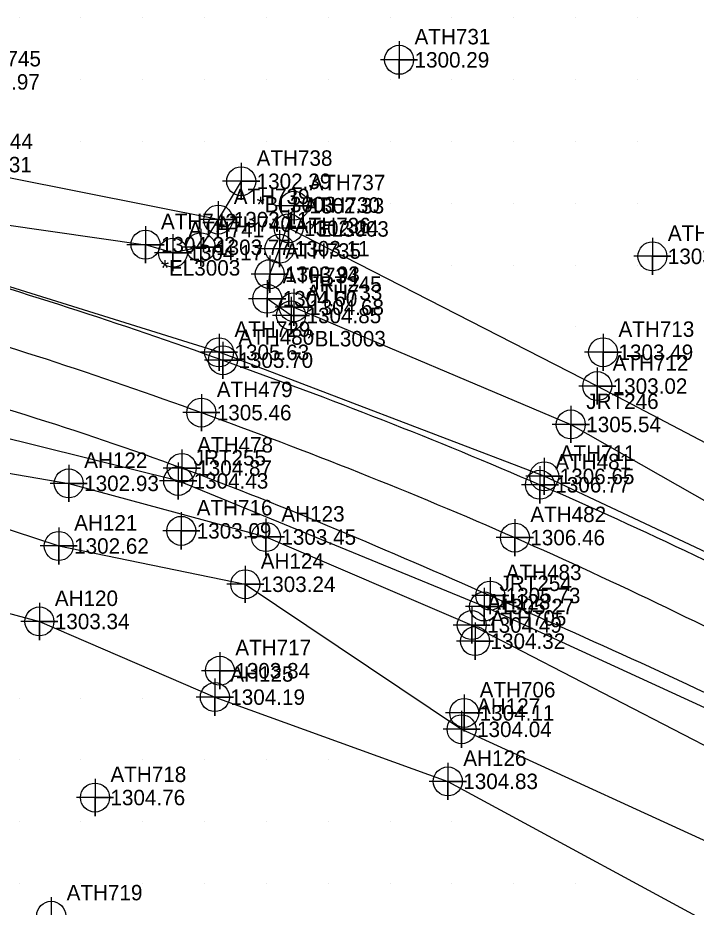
# Model space of a CAD drawing. Extents: x 1234484 to 1235382, y 695050 to 695510.
# Drawn here: x 1235049.8 to 1235159.5, y 695206.2 to 695350 of the extents above; entities that cross this region are included whole.
import ezdxf

# ---------------------------------------------------------------- set-up
doc = ezdxf.new("R2010")
doc.units = 0
for name, color, linetype in [('Exist DTM Breakline', 7, 'Continuous'), ('Exist DTM Breakline Cogo Elevation', 7, 'Continuous'), ('Exist DTM Breakline Cogo Number', 7, 'Continuous'), ('Exist DTM Breakline Cogo Point CELL', 7, 'Continuous'), ('Exist DTM Breakline Underwater', 7, 'Continuous'), ('Exist DTM Crownline', 7, 'Continuous'), ('Exist DTM Crownline Cogo Elevation', 7, 'Continuous'), ('Exist DTM Crownline Cogo Number', 7, 'Continuous'), ('Exist DTM Crownline Cogo Point CELL', 7, 'Continuous'), ('Exist DTM Drainline Cogo Elevation', 7, 'Continuous'), ('Exist DTM Drainline Cogo Number', 7, 'Continuous'), ('Exist DTM Drainline Cogo Point CELL', 7, 'Continuous'), ('Exist DTM QL2 LIDAR Elevation Point', 7, 'Continuous'), ('Exist DTM Regular Point CELL', 7, 'Continuous'), ('Exist DTM Regular Point Cogo Elevation', 7, 'Continuous'), ('Exist DTM Regular Point Cogo Number', 7, 'Continuous'), ('Exist DTM Regular Point Underwater CELL', 7, 'Continuous'), ('Exist DTM Regular Point Underwater Cogo Elevation', 7, 'Continuous'), ('Exist DTM Regular Point Underwater Cogo Number', 7, 'Continuous'), ('Exist Hydro Stream or Body of Water', 7, 'Continuous'), ('Exist Roads EOP', 7, 'Continuous'), ('Exist Roads EOP Cogo Elevation', 7, 'Continuous'), ('Exist Roads EOP Cogo Number', 7, 'Continuous'), ('Exist Roads EOP Cogo Point CELL', 7, 'Continuous'), ('Exist Roads EOP Other', 7, 'Continuous'), ('Exist Roads EOP Other Cogo Comment', 7, 'Continuous'), ('Exist Roads EOP Other Cogo Elevation', 7, 'Continuous'), ('Exist Roads EOP Other Cogo Number', 7, 'Continuous'), ('Exist Roads EOP Other Cogo Point CELL', 7, 'Continuous')]:
    doc.layers.add(name, color=color, linetype=linetype)

msp = doc.modelspace()

# ---------------------------------------------------------------- linework, layer by layer
at = {"layer": 'Exist DTM Breakline'}
for points in [[(1235082.217, 695317.363), (1235037.46, 695326.259), (1235017.524, 695333.883)], [(1235011.557, 695329.402), (1235031.782, 695318.825), (1235070.444, 695313.308)], [(1235319.256, 695177.55), (1235278.534, 695201.47), (1235237.781, 695224.217), (1235188.481, 695250.698), (1235134.96, 695275.849), (1235082.338, 695295.901), (1235034.938, 695310.723), (1234997.435, 695322.999)], [(1235324.566, 695184.553), (1235284.54, 695210.684), (1235243.923, 695233.555), (1235196.6, 695262.635), (1235143.527, 695290.446), (1235093.587, 695315.971)], [(1235094.433, 695303.192), (1235139.249, 695284.24), (1235185.145, 695258.152), (1235235.18, 695232.365), (1235270.796, 695206.904), (1235315.147, 695184.076)], [(1235258.778, 695187.05), (1235221.35, 695207.416), (1235173.519, 695232.644), (1235125.211, 695254.804), (1235075.73, 695275.107), (1235023.735, 695288.012), (1234968.789, 695301.22)]]:
    msp.add_lwpolyline(points, dxfattribs=at)
at = {"layer": 'Exist DTM Breakline Cogo Point CELL'}
for points in [[(1235093.587, 695318.971), (1235093.587, 695312.971), (1235093.587, 695315.971), (1235096.587, 695315.971), (1235090.587, 695315.971)], [(1235094.433, 695306.192), (1235094.433, 695300.192), (1235094.433, 695303.192), (1235097.433, 695303.192), (1235091.433, 695303.192)], [(1235082.338, 695298.901), (1235082.338, 695292.901), (1235082.338, 695295.901), (1235085.338, 695295.901), (1235079.338, 695295.901)], [(1235143.527, 695293.446), (1235143.527, 695287.446), (1235143.527, 695290.446), (1235146.527, 695290.446), (1235140.527, 695290.446)], [(1235139.249, 695287.24), (1235139.249, 695281.24), (1235139.249, 695284.24), (1235142.249, 695284.24), (1235136.249, 695284.24)], [(1235134.96, 695278.849), (1235134.96, 695272.849), (1235134.96, 695275.849), (1235137.96, 695275.849), (1235131.96, 695275.849)], [(1235075.73, 695278.107), (1235075.73, 695272.107), (1235075.73, 695275.107), (1235078.73, 695275.107), (1235072.73, 695275.107)], [(1235076.225, 695270.03), (1235076.225, 695264.03), (1235076.225, 695267.03), (1235079.225, 695267.03), (1235073.225, 695267.03)], [(1235125.211, 695257.804), (1235125.211, 695251.804), (1235125.211, 695254.804), (1235128.211, 695254.804), (1235122.211, 695254.804)], [(1235123.766, 695252.2), (1235123.766, 695246.2), (1235123.766, 695249.2), (1235126.766, 695249.2), (1235120.766, 695249.2)], [(1235055.183, 695207.784), (1235055.183, 695201.784), (1235055.183, 695204.784), (1235058.183, 695204.784), (1235052.183, 695204.784)]]:
    msp.add_lwpolyline(points, dxfattribs=at)
for centre in [(1235093.587, 695315.971), (1235094.433, 695303.192), (1235082.338, 695295.901), (1235143.527, 695290.446), (1235139.249, 695284.24), (1235075.73, 695275.107), (1235134.96, 695275.849), (1235076.225, 695267.03), (1235125.211, 695254.804), (1235123.766, 695249.2), (1235055.183, 695204.784)]:
    msp.add_circle(centre, 2.344, dxfattribs=at)
at = {"layer": 'Exist DTM Breakline Underwater'}
msp.add_lwpolyline([(1234948.239, 695292.841), (1234952.805, 695292.84), (1234960.83, 695292.864), (1234972.599, 695288.481), (1235023.203, 695275.502), (1235056.399, 695264.585), (1235086.587, 695258.395), (1235121.582, 695234.941), (1235168.445, 695213.485), (1235191.313, 695204.186), (1235209.05, 695188.429), (1235246.922, 695166.749), (1235265.478, 695149.496)], dxfattribs=at)
at = {"layer": 'Exist DTM Crownline'}
msp.add_spline([(1234978.534, 695313.159), (1235028.867, 695302.317), (1235079.475, 695286.154), (1235130.202, 695265.942), (1235178.94, 695242.599), (1235226.8, 695217.474)], degree=3, dxfattribs=at)
at = {"layer": 'Exist DTM Crownline Cogo Point CELL'}
for points in [[(1235079.475, 695289.154), (1235079.475, 695283.154), (1235079.475, 695286.154), (1235082.475, 695286.154), (1235076.475, 695286.154)], [(1235130.202, 695268.942), (1235130.202, 695262.942), (1235130.202, 695265.942), (1235133.202, 695265.942), (1235127.202, 695265.942)]]:
    msp.add_lwpolyline(points, dxfattribs=at)
for centre in [(1235079.475, 695286.154), (1235130.202, 695265.942)]:
    msp.add_circle(centre, 2.344, dxfattribs=at)
at = {"layer": 'Exist DTM Drainline Cogo Point CELL'}
for points in [[(1235058.02, 695277.707), (1235058.02, 695271.707), (1235058.02, 695274.707), (1235061.02, 695274.707), (1235055.02, 695274.707)], [(1235089.925, 695269.038), (1235089.925, 695263.038), (1235089.925, 695266.038), (1235092.925, 695266.038), (1235086.925, 695266.038)], [(1235053.271, 695255.381), (1235053.271, 695249.381), (1235053.271, 695252.381), (1235056.271, 695252.381), (1235050.271, 695252.381)], [(1235123.219, 695254.801), (1235123.219, 695248.801), (1235123.219, 695251.801), (1235126.219, 695251.801), (1235120.219, 695251.801)], [(1235081.661, 695243.144), (1235081.661, 695237.144), (1235081.661, 695240.144), (1235084.661, 695240.144), (1235078.661, 695240.144)], [(1235119.353, 695229.521), (1235119.353, 695223.521), (1235119.353, 695226.521), (1235122.353, 695226.521), (1235116.353, 695226.521)]]:
    msp.add_lwpolyline(points, dxfattribs=at)
for centre in [(1235058.02, 695274.707), (1235089.925, 695266.038), (1235053.271, 695252.381), (1235123.219, 695251.801), (1235081.661, 695240.144), (1235119.353, 695226.521)]:
    msp.add_circle(centre, 2.344, dxfattribs=at)
at = {"layer": 'Exist DTM QL2 LIDAR Elevation Point'}
for p, q in [((1235050, 695350), (1235050, 695350)), ((1235060, 695350), (1235060, 695350)), ((1235070, 695350), (1235070, 695350)), ((1235080, 695350), (1235080, 695350)), ((1235090, 695350), (1235090, 695350)), ((1235100, 695350), (1235100, 695350)), ((1235110, 695350), (1235110, 695350)), ((1235120, 695350), (1235120, 695350)), ((1235130, 695350), (1235130, 695350)), ((1235140, 695350), (1235140, 695350)), ((1235150, 695350), (1235150, 695350)), ((1235050, 695340), (1235050, 695340)), ((1235060, 695340), (1235060, 695340)), ((1235070, 695340), (1235070, 695340)), ((1235080, 695340), (1235080, 695340)), ((1235090, 695340), (1235090, 695340)), ((1235100, 695340), (1235100, 695340)), ((1235110, 695340), (1235110, 695340)), ((1235120, 695340), (1235120, 695340)), ((1235130, 695340), (1235130, 695340)), ((1235140, 695340), (1235140, 695340)), ((1235150, 695340), (1235150, 695340)), ((1235050, 695330), (1235050, 695330)), ((1235060, 695330), (1235060, 695330)), ((1235070, 695330), (1235070, 695330)), ((1235080, 695330), (1235080, 695330)), ((1235090, 695330), (1235090, 695330)), ((1235100, 695330), (1235100, 695330)), ((1235110, 695330), (1235110, 695330)), ((1235120, 695330), (1235120, 695330)), ((1235130, 695330), (1235130, 695330)), ((1235140, 695330), (1235140, 695330)), ((1235150, 695330), (1235150, 695330)), ((1235100, 695320), (1235100, 695320)), ((1235110, 695320), (1235110, 695320)), ((1235120, 695320), (1235120, 695320)), ((1235130, 695320), (1235130, 695320)), ((1235140, 695320), (1235140, 695320)), ((1235150, 695320), (1235150, 695320)), ((1235120, 695310), (1235120, 695310)), ((1235130, 695310), (1235130, 695310)), ((1235140, 695310), (1235140, 695310)), ((1235150, 695310), (1235150, 695310)), ((1235140, 695300), (1235140, 695300)), ((1235150, 695300), (1235150, 695300)), ((1235050, 695240), (1235050, 695240)), ((1235060, 695240), (1235060, 695240)), ((1235070, 695240), (1235070, 695240)), ((1235050, 695230), (1235050, 695230)), ((1235060, 695230), (1235060, 695230)), ((1235070, 695230), (1235070, 695230)), ((1235080, 695230), (1235080, 695230)), ((1235090, 695230), (1235090, 695230)), ((1235100, 695230), (1235100, 695230)), ((1235050, 695220), (1235050, 695220)), ((1235060, 695220), (1235060, 695220)), ((1235070, 695220), (1235070, 695220)), ((1235080, 695220), (1235080, 695220)), ((1235090, 695220), (1235090, 695220)), ((1235100, 695220), (1235100, 695220)), ((1235110, 695220), (1235110, 695220)), ((1235120, 695220), (1235120, 695220)), ((1235050, 695210), (1235050, 695210)), ((1235060, 695210), (1235060, 695210)), ((1235070, 695210), (1235070, 695210)), ((1235080, 695210), (1235080, 695210)), ((1235090, 695210), (1235090, 695210)), ((1235100, 695210), (1235100, 695210)), ((1235110, 695210), (1235110, 695210)), ((1235120, 695210), (1235120, 695210)), ((1235130, 695210), (1235130, 695210)), ((1235140, 695210), (1235140, 695210))]:
    msp.add_line(p, q, dxfattribs=at)
at = {"layer": 'Exist DTM Regular Point CELL'}
for points in [[(1235111.473, 695346.202), (1235111.473, 695340.202), (1235111.473, 695343.202), (1235114.473, 695343.202), (1235108.473, 695343.202)], [(1235152.448, 695314.425), (1235152.448, 695308.425), (1235152.448, 695311.425), (1235155.448, 695311.425), (1235149.448, 695311.425)], [(1235144.466, 695298.905), (1235144.466, 695292.905), (1235144.466, 695295.905), (1235147.466, 695295.905), (1235141.466, 695295.905)], [(1235062.271, 695226.906), (1235062.271, 695220.906), (1235062.271, 695223.906), (1235065.271, 695223.906), (1235059.271, 695223.906)]]:
    msp.add_lwpolyline(points, dxfattribs=at)
for centre in [(1235111.473, 695343.202), (1235152.448, 695311.425), (1235144.466, 695295.905), (1235062.271, 695223.906)]:
    msp.add_circle(centre, 2.344, dxfattribs=at)
at = {"layer": 'Exist DTM Regular Point Underwater CELL'}
for points in [[(1235056.399, 695267.585), (1235056.399, 695261.585), (1235056.399, 695264.585), (1235059.399, 695264.585), (1235053.399, 695264.585)], [(1235086.587, 695261.395), (1235086.587, 695255.395), (1235086.587, 695258.395), (1235089.587, 695258.395), (1235083.587, 695258.395)], [(1235082.475, 695247.412), (1235082.475, 695241.412), (1235082.475, 695244.412), (1235085.475, 695244.412), (1235079.475, 695244.412)], [(1235122.003, 695240.589), (1235122.003, 695234.589), (1235122.003, 695237.589), (1235125.003, 695237.589), (1235119.003, 695237.589)], [(1235121.582, 695237.941), (1235121.582, 695231.941), (1235121.582, 695234.941), (1235124.582, 695234.941), (1235118.582, 695234.941)]]:
    msp.add_lwpolyline(points, dxfattribs=at)
for centre in [(1235056.399, 695264.585), (1235086.587, 695258.395), (1235082.475, 695244.412), (1235122.003, 695237.589), (1235121.582, 695234.941)]:
    msp.add_circle(centre, 2.344, dxfattribs=at)
at = {"layer": 'Exist Hydro Stream or Body of Water'}
for points in [[(1235024.437, 695280.431), (1235058.02, 695274.707), (1235089.925, 695266.038), (1235123.219, 695251.801), (1235172.108, 695226.531), (1235193.345, 695212.706), (1235213.169, 695197.447), (1235252.346, 695179.593), (1235273.059, 695163.484)], [(1235018.754, 695261.568), (1235053.271, 695252.381), (1235081.661, 695240.144), (1235119.353, 695226.521), (1235169.371, 695199.43), (1235188.125, 695189.805), (1235205.75, 695183.352), (1235242.093, 695153.734), (1235263.468, 695141.323)]]:
    msp.add_lwpolyline(points, dxfattribs=at)
at = {"layer": 'Exist Roads EOP'}
for points in [[(1234989.744, 695321.275), (1235032.632, 695310.758), (1235082.97, 695294.625), (1235134.247, 695274.482), (1235183.928, 695250.955), (1235232.115, 695225.68)], [(1234969.592, 695304.589), (1235025.451, 695292.964), (1235076.313, 695277.193), (1235126.218, 695256.569), (1235174.523, 695234.324), (1235222.247, 695208.988)]]:
    msp.add_spline(points, degree=3, dxfattribs=at)
at = {"layer": 'Exist Roads EOP Cogo Point CELL'}
for points in [[(1235082.97, 695297.625), (1235082.97, 695291.625), (1235082.97, 695294.625), (1235085.97, 695294.625), (1235079.97, 695294.625)], [(1235076.313, 695280.193), (1235076.313, 695274.193), (1235076.313, 695277.193), (1235079.313, 695277.193), (1235073.313, 695277.193)], [(1235134.247, 695277.482), (1235134.247, 695271.482), (1235134.247, 695274.482), (1235137.247, 695274.482), (1235131.247, 695274.482)], [(1235126.218, 695259.569), (1235126.218, 695253.569), (1235126.218, 695256.569), (1235129.218, 695256.569), (1235123.218, 695256.569)]]:
    msp.add_lwpolyline(points, dxfattribs=at)
for centre in [(1235082.97, 695294.625), (1235076.313, 695277.193), (1235134.247, 695274.482), (1235126.218, 695256.569)]:
    msp.add_circle(centre, 2.344, dxfattribs=at)
at = {"layer": 'Exist Roads EOP Other'}
for points in [[(1235085.921, 695323.562), (1235082.217, 695317.363), (1235079.371, 695312.89), (1235074.885, 695312.014), (1235070.444, 695313.308)], [(1235093.995, 695301.858), (1235090.13, 695304.57), (1235090.534, 695308.536), (1235092.1, 695312.656), (1235094.477, 695319.605)]]:
    msp.add_lwpolyline(points, dxfattribs=at)
at = {"layer": 'Exist Roads EOP Other Cogo Point CELL'}
for points in [[(1235085.921, 695326.562), (1235085.921, 695320.562), (1235085.921, 695323.562), (1235088.921, 695323.562), (1235082.921, 695323.562)], [(1235094.477, 695322.605), (1235094.477, 695316.605), (1235094.477, 695319.605), (1235097.477, 695319.605), (1235091.477, 695319.605)], [(1235082.217, 695320.363), (1235082.217, 695314.363), (1235082.217, 695317.363), (1235085.217, 695317.363), (1235079.217, 695317.363)], [(1235070.444, 695316.308), (1235070.444, 695310.308), (1235070.444, 695313.308), (1235073.444, 695313.308), (1235067.444, 695313.308)], [(1235079.371, 695315.89), (1235079.371, 695309.89), (1235079.371, 695312.89), (1235082.371, 695312.89), (1235076.371, 695312.89)], [(1235074.885, 695315.014), (1235074.885, 695309.014), (1235074.885, 695312.014), (1235077.885, 695312.014), (1235071.885, 695312.014)], [(1235092.1, 695315.656), (1235092.1, 695309.656), (1235092.1, 695312.656), (1235095.1, 695312.656), (1235089.1, 695312.656)], [(1235090.534, 695311.536), (1235090.534, 695305.536), (1235090.534, 695308.536), (1235093.534, 695308.536), (1235087.534, 695308.536)], [(1235090.13, 695307.57), (1235090.13, 695301.57), (1235090.13, 695304.57), (1235093.13, 695304.57), (1235087.13, 695304.57)], [(1235093.995, 695304.858), (1235093.995, 695298.858), (1235093.995, 695301.858), (1235096.995, 695301.858), (1235090.995, 695301.858)]]:
    msp.add_lwpolyline(points, dxfattribs=at)
for centre in [(1235085.921, 695323.562), (1235094.477, 695319.605), (1235082.217, 695317.363), (1235070.444, 695313.308), (1235074.885, 695312.014), (1235079.371, 695312.89), (1235092.1, 695312.656), (1235090.534, 695308.536), (1235090.13, 695304.57), (1235093.995, 695301.858)]:
    msp.add_circle(centre, 2.344, dxfattribs=at)

# ---------------------------------------------------------------- texts
at = {"layer": 'Exist DTM Breakline Cogo Elevation'}
for s, p in [('1302.31', (1235039.96, 695325.009)), ('1302.24', (1235096.087, 695314.721)), ('1304.68', (1235096.933, 695301.942)), ('1305.63', (1235084.838, 695294.651)), ('1303.02', (1235146.027, 695289.196)), ('1305.54', (1235141.749, 695282.99)), ('1306.65', (1235137.46, 695274.599)), ('1304.43', (1235078.23, 695273.857)), ('1303.09', (1235078.725, 695265.78)), ('1305.27', (1235127.711, 695253.554)), ('1304.32', (1235126.266, 695247.95))]:
    msp.add_text(s, height=2.5, dxfattribs=at).set_placement(p)
at = {"layer": 'Exist DTM Breakline Cogo Number'}
for s, p in [('ATH744', (1235039.96, 695328.759)), ('ATH730', (1235096.087, 695318.471)), ('JRT245', (1235096.933, 695305.692)), ('ATH729', (1235084.838, 695298.401)), ('ATH712', (1235146.027, 695292.946)), ('JRT246', (1235141.749, 695286.74)), ('JRT255', (1235078.23, 695277.607)), ('ATH711', (1235137.46, 695278.349)), ('ATH716', (1235078.725, 695269.53)), ('JRT254', (1235127.711, 695257.304)), ('ATH705', (1235126.266, 695251.7)), ('ATH719', (1235057.683, 695207.284))]:
    msp.add_text(s, height=2.5, dxfattribs=at).set_placement(p)
at = {"layer": 'Exist DTM Crownline Cogo Elevation'}
for s, p in [('1305.46', (1235081.975, 695284.904)), ('1306.46', (1235132.702, 695264.692))]:
    msp.add_text(s, height=2.5, dxfattribs=at).set_placement(p)
at = {"layer": 'Exist DTM Crownline Cogo Number'}
for s, p in [('ATH479', (1235081.975, 695288.654)), ('ATH482', (1235132.702, 695268.442))]:
    msp.add_text(s, height=2.5, dxfattribs=at).set_placement(p)
at = {"layer": 'Exist DTM Drainline Cogo Elevation'}
for s, p in [('1302.93', (1235060.52, 695273.457)), ('1303.45', (1235092.425, 695264.788)), ('1303.34', (1235055.771, 695251.131)), ('1304.49', (1235125.719, 695250.551)), ('1304.19', (1235084.161, 695238.894)), ('1304.83', (1235121.853, 695225.271))]:
    msp.add_text(s, height=2.5, dxfattribs=at).set_placement(p)
at = {"layer": 'Exist DTM Drainline Cogo Number'}
for s, p in [('AH122', (1235060.52, 695277.207)), ('AH123', (1235092.425, 695268.538)), ('AH120', (1235055.771, 695254.881)), ('AH128', (1235125.719, 695254.301)), ('AH125', (1235084.161, 695242.644)), ('AH126', (1235121.853, 695229.021))]:
    msp.add_text(s, height=2.5, dxfattribs=at).set_placement(p)
at = {"layer": 'Exist DTM Regular Point Cogo Elevation'}
for s, p in [('1300.29', (1235113.973, 695341.952)), ('1301.97', (1235041.262, 695338.386)), ('1303.15', (1235154.948, 695310.175)), ('1303.49', (1235146.966, 695294.655)), ('1304.76', (1235064.771, 695222.656))]:
    msp.add_text(s, height=2.5, dxfattribs=at).set_placement(p)
at = {"layer": 'Exist DTM Regular Point Cogo Number'}
for s, p in [('ATH731', (1235113.973, 695345.702)), ('ATH745', (1235041.262, 695342.136)), ('ATH714', (1235154.948, 695313.925)), ('ATH713', (1235146.966, 695298.405)), ('ATH718', (1235064.771, 695226.406))]:
    msp.add_text(s, height=2.5, dxfattribs=at).set_placement(p)
at = {"layer": 'Exist DTM Regular Point Underwater Cogo Elevation'}
for s, p in [('1302.62', (1235058.899, 695263.335)), ('1303.24', (1235089.087, 695257.145)), ('1303.84', (1235084.975, 695243.162)), ('1304.11', (1235124.503, 695236.339)), ('1304.04', (1235124.082, 695233.691))]:
    msp.add_text(s, height=2.5, dxfattribs=at).set_placement(p)
at = {"layer": 'Exist DTM Regular Point Underwater Cogo Number'}
for s, p in [('AH121', (1235058.899, 695267.085)), ('AH124', (1235089.087, 695260.895)), ('ATH717', (1235084.975, 695246.912)), ('ATH706', (1235124.503, 695240.089)), ('AH127', (1235124.082, 695237.441))]:
    msp.add_text(s, height=2.5, dxfattribs=at).set_placement(p)
at = {"layer": 'Exist Roads EOP Cogo Elevation'}
for s, p in [('1305.70', (1235085.47, 695293.375)), ('1304.87', (1235078.813, 695275.943)), ('1306.77', (1235136.747, 695273.232)), ('1305.73', (1235128.718, 695255.319))]:
    msp.add_text(s, height=2.5, dxfattribs=at).set_placement(p)
at = {"layer": 'Exist Roads EOP Cogo Number'}
for s, p in [('ATH480', (1235085.47, 695297.125)), ('ATH478', (1235078.813, 695279.693)), ('ATH481', (1235136.747, 695276.982)), ('ATH483', (1235128.718, 695259.069))]:
    msp.add_text(s, height=2.5, dxfattribs=at).set_placement(p)
at = {"layer": 'Exist Roads EOP Other Cogo Comment'}
for s, p in [('*BL3003', (1235088.421, 695318.562)), ('*EL3003', (1235096.977, 695314.605)), ('*EL3003', (1235072.944, 695308.308)), ('*BL3003', (1235096.495, 695296.858))]:
    msp.add_text(s, height=2.5, dxfattribs=at).set_placement(p)
at = {"layer": 'Exist Roads EOP Other Cogo Elevation'}
for s, p in [('1302.39', (1235088.421, 695322.312)), ('1302.33', (1235096.977, 695318.355)), ('1303.11', (1235084.717, 695316.113)), ('1304.32', (1235072.944, 695312.058)), ('1304.17', (1235077.385, 695310.764)), ('1303.77', (1235081.871, 695311.64)), ('1303.11', (1235094.6, 695311.406)), ('1303.93', (1235093.034, 695307.286)), ('1304.60', (1235092.63, 695303.32)), ('1304.85', (1235096.495, 695300.608))]:
    msp.add_text(s, height=2.5, dxfattribs=at).set_placement(p)
at = {"layer": 'Exist Roads EOP Other Cogo Number'}
for s, p in [('ATH738', (1235088.421, 695326.062)), ('ATH737', (1235096.977, 695322.105)), ('ATH739', (1235084.717, 695319.863)), ('ATH742', (1235072.944, 695315.808)), ('ATH740', (1235081.871, 695315.39)), ('ATH736', (1235094.6, 695315.156)), ('ATH741', (1235077.385, 695314.514)), ('ATH735', (1235093.034, 695311.036)), ('ATH734', (1235092.63, 695307.07)), ('ATH733', (1235096.495, 695304.358))]:
    msp.add_text(s, height=2.5, dxfattribs=at).set_placement(p)

doc.saveas('drawing.dxf')
